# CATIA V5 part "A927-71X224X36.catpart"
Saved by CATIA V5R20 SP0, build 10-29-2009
Part number: A927-71X224X36
Source: Unknown
Property "A": "36.000"
Property "ARTICLENO": "A927-71X224X36"
Property "BOMINFO": "A927-71X224X36"
Property "CODE": "A927-71X224X36"
Property "CREATOR": "CADENAS GmbH"
Property "D": "14.000"
Property "D1": "20.000"
Property "F": "18.000"
Property "FORM": "A"
Property "L": "224.000"
Property "L1": "90.000"
Property "L2": "20.000"
Property "L3": "50.000"
Property "LINA": "A927-71X224X36"
Property "NB": "A927-71X224X36"
Property "NBSYN": "$CODE."
Property "NN": "A927"
Property "NT": "VDI 3387 Removable Die Heels, steel and self-lubricating"
Property "R": "16.000"
Property "S": "36.000"
Property "SUPPLIER": "CF"
Property "T": "16.000"
Property "W": "71.000"
Bounding box of the stored display mesh (mm): x -35.5 to 35.5, y 0 to 224, z -36 to 0
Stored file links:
  C:\Users\borellobunino\Desktop\3D X SITO CF\A927\GSB_OILLESS_G2290507122436\CATIAV5\A927-71X224X36.catpart
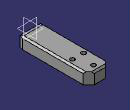
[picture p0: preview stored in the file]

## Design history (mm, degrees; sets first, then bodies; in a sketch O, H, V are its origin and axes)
Body1 "Geometry.1" (main body)
  Solid1 "A927-71X224X36catpart": solid without history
